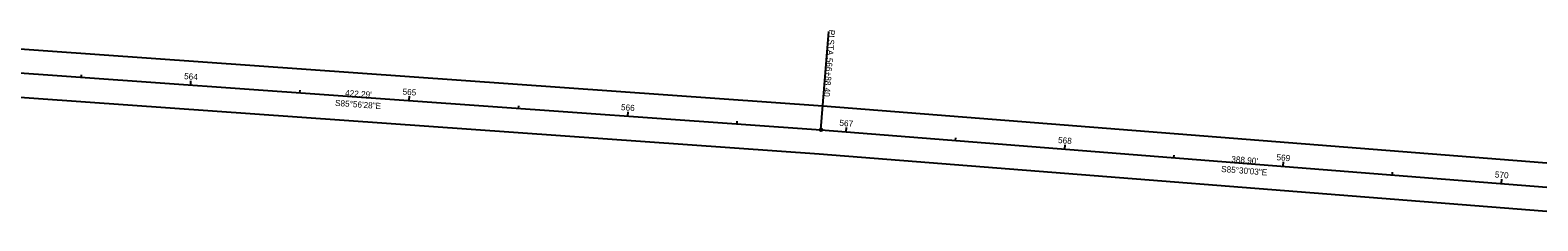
# Model space of a CAD drawing. Extents: x 1898481 to 1901152, y 703119 to 703373.
# Drawn here: x 1899807 to 1900495, y 703161 to 703248 of the extents above; entities that cross this region are included whole.
import ezdxf

# ---------------------------------------------------------------- set-up
doc = ezdxf.new("R2010")
doc.units = 0
for name, color, linetype in [('_CIVIL_CONSTRUCTION', 7, 'Continuous'), ('DT_P_Terrain_Boundary', 7, 'Continuous'), ('DT_P_Triangles', 7, 'Continuous'), ('PF_X_Ground_Line', 7, 'Continuous'), ('PV_P_EOP', 7, 'Continuous'), ('SC_Scratch1', 7, 'Continuous')]:
    doc.layers.add(name, color=color, linetype=linetype)

msp = doc.modelspace()

# ---------------------------------------------------------------- linework, layer by layer
at = {"layer": '_CIVIL_CONSTRUCTION'}
msp.add_line((1900167.56, 703202.61), (1900171.09, 703247.47), dxfattribs=at)
msp.add_circle((1900167.56, 703202.61), 0.6, dxfattribs=at)
at = {"layer": 'DT_P_Triangles'}
for p, q in [((1899830.01, 703226.56), (1899830.09, 703227.76)), ((1899879.88, 703223.03), (1899880.02, 703225.02)), ((1899929.76, 703219.49), (1899929.84, 703220.68)), ((1899979.63, 703215.95), (1899979.77, 703217.94)), ((1900029.51, 703212.41), (1900029.59, 703213.6)), ((1900079.38, 703208.87), (1900079.52, 703210.86)), ((1900129.26, 703205.33), (1900129.34, 703206.53)), ((1900179.12, 703201.7), (1900179.28, 703203.7)), ((1900228.97, 703197.78), (1900229.06, 703198.98)), ((1900278.81, 703193.86), (1900278.97, 703195.85)), ((1900328.66, 703189.93), (1900328.75, 703191.13)), ((1900378.51, 703186.01), (1900378.66, 703188.01)), ((1900428.35, 703182.09), (1900428.45, 703183.29)), ((1900478.2, 703178.17), (1900478.36, 703180.16))]:
    msp.add_line(p, q, dxfattribs=at)
at = {"layer": 'PV_P_EOP'}
for p, q in [((1899747.12, 703243.47), (1900168.38, 703213.58)), ((1899745.53, 703221.53), (1900166.74, 703191.64)), ((1900168.38, 703213.58), (1900556.08, 703183.07)), ((1900166.74, 703191.64), (1900554.44, 703161.13))]:
    msp.add_line(p, q, dxfattribs=at)
at = {"layer": 'SC_Scratch1'}
for p, q in [((1899746.33, 703232.5), (1900167.56, 703202.61)), ((1900167.56, 703202.61), (1900555.26, 703172.1))]:
    msp.add_line(p, q, dxfattribs=at)

# ---------------------------------------------------------------- texts
at = {"layer": '_CIVIL_CONSTRUCTION'}
for s, p in [(' STA. ', (1900170.94, 703244.98)), ('PI', (1900171.2, 703248.36)), ('566+88.40', (1900170.19, 703235.56))]:
    msp.add_text(s, height=2.8, rotation=265.5007, dxfattribs=at).set_placement(p)
at = {"layer": 'DT_P_Terrain_Boundary'}
for s, rotation, p in [("422.29'", 355.94115, (1899950.28, 703218.07)), ("388.90'", 355.5007, (1900354.75, 703187.92))]:
    msp.add_text(s, height=2.8, rotation=rotation, dxfattribs=at).set_placement(p)
at = {"layer": 'DT_P_Triangles'}
for s, rotation, p in [('564', 355.94115, (1899876.8, 703225.75)), ('565', 355.94115, (1899976.51, 703218.67)), ('566', 355.94115, (1900076.21, 703211.6)), ('567', 355.5007, (1900175.91, 703204.46)), ('568', 355.5007, (1900275.69, 703196.61)), ('569', 355.5007, (1900375.39, 703188.77)), ('570', 355.5007, (1900475.06, 703180.92))]:
    msp.add_text(s, height=2.8, rotation=rotation, dxfattribs=at).set_placement(p)
at = {"layer": 'PF_X_Ground_Line'}
for s, rotation, p in [('S85°56\'28"E', 355.94115, (1899945.69, 703213.54)), ('S85°30\'03"E', 355.5007, (1900350.13, 703183.43))]:
    msp.add_text(s, height=2.8, rotation=rotation, dxfattribs=at).set_placement(p)

doc.saveas('drawing.dxf')
